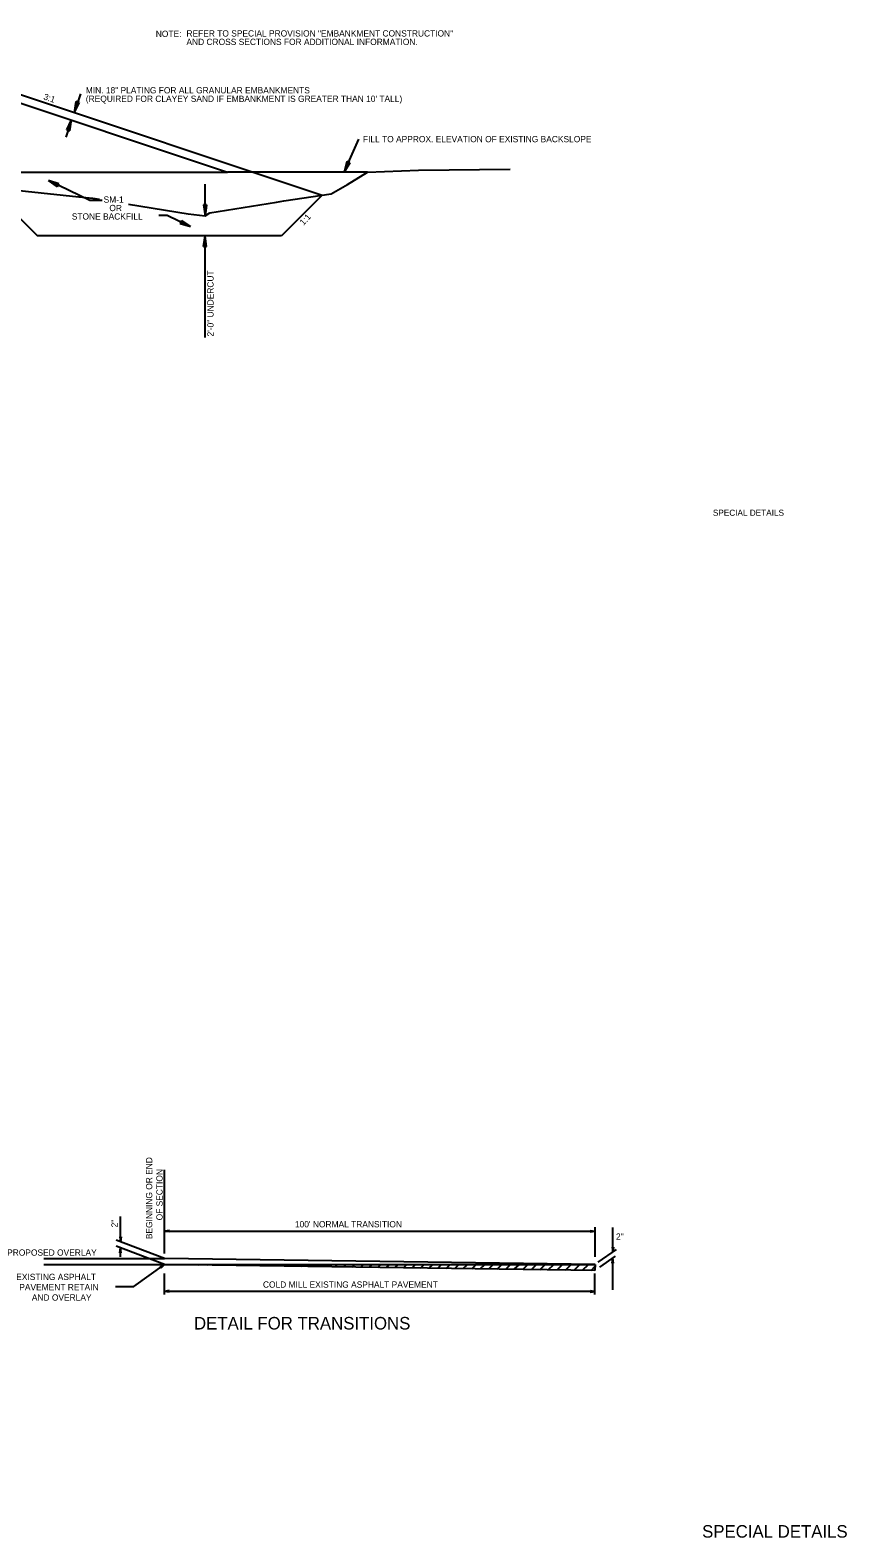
# Model space of a CAD drawing. Extents: x 1035 to 3550, y 35 to 1510.
# Drawn here: x 2769 to 3550, y 35 to 1477 of the extents above; entities that cross this region are included whole.
import ezdxf

# ---------------------------------------------------------------- set-up
doc = ezdxf.new("R2010")
doc.units = 0
for name, color, linetype in [('Default', 7, 'Continuous'), ('G-ANNO-NPLT', 7, 'Continuous'), ('R_Border', 7, 'Continuous'), ('R_Border Notes', 7, 'Continuous'), ('R_Border Prem', 7, 'Continuous'), ('R_Detour Annot', 7, 'Continuous'), ('R_Exist Surface', 7, 'Continuous'), ('R_Fin Surface', 7, 'Continuous'), ('R_Grid', 7, 'Continuous')]:
    doc.layers.add(name, color=color, linetype=linetype)

msp = doc.modelspace()

# ---------------------------------------------------------------- linework, layer by layer
at = {"layer": 'Default'}
for p, q in [((2982.4, 1341.5), (2958, 1341.5)), ((2897.9, 307.1), (2897.9, 387)), ((2855.7, 318.4), (2855.7, 342.4)), ((3309.4, 304), (3309.4, 332.4)), ((3326.3, 308.4), (3326.3, 332)), ((2897.9, 302.4), (2851.5, 319.8)), ((2855, 322.9), (2855.7, 318.4)), ((2855, 322.9), (2855.7, 319.1)), ((2856.3, 322.9), (2855, 322.9)), ((2855.2, 322.9), (2855.7, 320)), ((2855.2, 322.9), (2855.7, 320.7)), ((2855.5, 322.9), (2855.7, 321.5)), ((2855.5, 322.9), (2855.7, 322.2)), ((2856.3, 322.9), (2855.7, 318.4)), ((2855.9, 322.9), (2855.7, 321.5)), ((2856.1, 322.9), (2855.7, 320)), ((2856.1, 322.9), (2855.7, 319.1)), ((2855.9, 322.9), (2855.7, 320.7)), ((2855.7, 322.9), (2855.7, 322.2)), ((2902.5, 329.1), (2897.9, 328.4)), ((2897.9, 328.4), (3309.4, 328.4)), ((2902.5, 327.8), (2897.9, 328.4)), ((2902.5, 328.9), (2898.5, 328.4)), ((2902.5, 327.8), (2898.5, 328.4)), ((2902.5, 328.9), (2899.4, 328.4)), ((2902.5, 328), (2899.4, 328.4)), ((2902.5, 328.7), (2900.3, 328.4)), ((2902.5, 328), (2900.3, 328.4)), ((2902.5, 328.7), (2901, 328.4)), ((2902.5, 328.2), (2901, 328.4)), ((2902.5, 328.4), (2901.9, 328.4)), ((2902.5, 328.2), (2901.9, 328.4)), ((2902.5, 327.8), (2902.5, 329.1)), ((3304.8, 329.1), (3309.4, 328.4)), ((3304.8, 329.1), (3304.8, 327.8)), ((3304.8, 328.9), (3307.9, 328.4)), ((3304.8, 328.9), (3308.5, 328.4)), ((3304.8, 328.7), (3306.3, 328.4)), ((3304.8, 328.7), (3307, 328.4)), ((3304.8, 327.8), (3309.4, 328.4)), ((3304.8, 328.2), (3306.3, 328.4)), ((3304.8, 328), (3307.9, 328.4)), ((3304.8, 327.8), (3308.5, 328.4)), ((3304.8, 328), (3307, 328.4)), ((3304.8, 328.2), (3305.4, 328.4)), ((3304.8, 328.4), (3305.4, 328.4)), ((2897.9, 296.7), (2851.5, 314)), ((2855, 307.8), (2855.7, 312.4)), ((2855, 307.8), (2855.7, 311.8)), ((2855, 307.8), (2856.3, 307.8)), ((2855.2, 307.8), (2855.7, 310.9)), ((2855.2, 307.8), (2855.7, 310.2)), ((2855.5, 307.8), (2855.7, 309.3)), ((2855.5, 307.8), (2855.7, 308.4)), ((2856.3, 307.8), (2855.7, 312.4)), ((2855.7, 304), (2855.7, 312.4)), ((2856.1, 307.8), (2855.7, 311.8)), ((2856.1, 307.8), (2855.7, 310.9)), ((2855.9, 307.8), (2855.7, 310.2)), ((2855.9, 307.8), (2855.7, 309.3)), ((2855.7, 307.8), (2855.7, 308.4)), ((3312.5, 298.9), (3329.8, 310.9)), ((3313.9, 294), (3329, 304.7)), ((3325.6, 313.1), (3326.3, 308.4)), ((3327, 313.1), (3325.6, 313.1)), ((3325.9, 313.1), (3326.3, 310)), ((3325.9, 313.1), (3326.3, 309.3)), ((3326.1, 313.1), (3326.3, 311.6)), ((3326.1, 313.1), (3326.3, 310.9)), ((3327, 313.1), (3326.3, 308.4)), ((3326.5, 313.1), (3326.3, 311.6)), ((3326.7, 313.1), (3326.3, 310)), ((3327, 313.1), (3326.3, 309.3)), ((3326.7, 313.1), (3326.3, 310.9)), ((3326.3, 313.1), (3326.3, 312.4)), ((3326.5, 313.1), (3326.3, 312.4)), ((2782.4, 302.4), (2897.9, 302.4)), ((2782.4, 296.7), (3309.4, 296.7)), ((2868.6, 275.6), (2897.9, 296.7)), ((2893.7, 294.4), (2897.9, 296.7)), ((2893.7, 294.4), (2894.5, 293.3)), ((2893.9, 294.4), (2897.2, 296.2)), ((2893.9, 294.4), (2896.5, 295.8)), ((2893.9, 294.2), (2895.9, 295.3)), ((2893.9, 294.2), (2895.4, 294.9)), ((2894.1, 294), (2894.8, 294.4)), ((2894.1, 294), (2894.8, 294.4)), ((2894.3, 293.6), (2896.5, 295.8)), ((2894.3, 293.8), (2895.9, 295.3)), ((2894.3, 293.8), (2895.4, 294.9)), ((2894.5, 293.3), (2897.9, 296.7)), ((2894.5, 293.6), (2897.2, 296.2)), ((3309.4, 296.7), (2897.9, 302.4)), ((3309.2, 290.9), (2897.9, 296.7)), ((2914.1, 296.4), (2914.3, 296.7)), ((2922.2, 296.3), (2922.5, 296.7)), ((2930.3, 296.2), (2931, 296.7)), ((2938.6, 296.1), (2939.2, 296.7)), ((2946.7, 296), (2947.4, 296.7)), ((2954.8, 295.9), (2955.6, 296.7)), ((2962.9, 295.8), (2963.8, 296.7)), ((2971.2, 295.6), (2972.3, 296.7)), ((2979.3, 295.5), (2980.5, 296.7)), ((2987.7, 295.4), (2988.7, 296.7)), ((2995.6, 295.3), (2996.9, 296.7)), ((3003.9, 295.2), (3005.4, 296.7)), ((3012, 295.1), (3013.6, 296.7)), ((3020.3, 295), (3021.8, 296.7)), ((3028.2, 294.8), (3030.2, 296.7)), ((3036.5, 294.7), (3038.5, 296.7)), ((3044.6, 294.6), (3046.7, 296.7)), ((3052.7, 294.5), (3054.9, 296.7)), ((3060.8, 294.4), (3063.3, 296.7)), ((3069.2, 294.3), (3071.5, 296.7)), ((3077.3, 294.1), (3079.8, 296.7)), ((3085.4, 294), (3088, 296.7)), ((3093.5, 293.9), (3096.4, 296.7)), ((3101.8, 293.8), (3104.6, 296.7)), ((3109.7, 293.7), (3112.9, 296.7)), ((3118, 293.6), (3121.1, 296.7)), ((3126.3, 293.5), (3129.3, 296.7)), ((3134.4, 293.3), (3137.7, 296.7)), ((3142.5, 293.2), (3146, 296.7)), ((3150.6, 293.1), (3154.2, 296.7)), ((3159, 293), (3162.6, 296.7)), ((3167.1, 292.9), (3170.8, 296.7)), ((3175.2, 292.8), (3179.1, 296.7)), ((3183.3, 292.7), (3187.3, 296.7)), ((3191.6, 292.5), (3195.7, 296.7)), ((3199.5, 292.4), (3203.9, 296.7)), ((3207.8, 292.3), (3212.1, 296.7)), ((3215.9, 292.2), (3220.4, 296.7)), ((3224.2, 292.1), (3228.6, 296.7)), ((3232.1, 292), (3237, 296.7)), ((3240.4, 291.9), (3245.2, 296.7)), ((3248.6, 291.8), (3253.5, 296.7)), ((3256.6, 291.6), (3261.7, 296.7)), ((3264.7, 291.5), (3270.1, 296.7)), ((3273.1, 291.4), (3278.3, 296.7)), ((3281.2, 291.3), (3286.6, 296.7)), ((3289.3, 291.2), (3294.8, 296.7)), ((3297.4, 291.1), (3303.2, 296.7)), ((3305.7, 290.9), (3309.3, 294.6)), ((3309.4, 296.7), (3309.2, 290.9)), ((3325.6, 298), (3326.3, 302.7)), ((3325.6, 298), (3327, 298)), ((3325.9, 298), (3326.3, 302)), ((3325.9, 298), (3326.3, 301.1)), ((3326.1, 298), (3326.3, 300.4)), ((3326.1, 298), (3326.3, 299.5)), ((3326.3, 272.5), (3326.3, 302.7)), ((3327, 298), (3326.3, 302.7)), ((3327, 298), (3326.3, 302)), ((3326.7, 298), (3326.3, 301.1)), ((3326.7, 298), (3326.3, 300.4)), ((3326.5, 298), (3326.3, 299.5)), ((3326.5, 298), (3326.3, 298.9)), ((3326.3, 298), (3326.3, 298.9)), ((2851, 275.6), (2868.6, 275.6)), ((2897.9, 268), (2897.9, 288)), ((3309.2, 268), (3309.2, 288)), ((2902.3, 271.6), (2897.9, 270.9)), ((2902.3, 271.6), (2897.9, 270.9)), ((3309.2, 270.9), (2897.9, 270.9)), ((2902.3, 270.2), (2897.9, 270.9)), ((2902.3, 270.2), (2897.9, 270.9)), ((2902.3, 271.6), (2898.5, 270.9)), ((2902.3, 271.6), (2898.5, 270.9)), ((2902.3, 270.5), (2898.5, 270.9)), ((2902.3, 270.5), (2898.5, 270.9)), ((2902.3, 271.4), (2899.4, 270.9)), ((2902.3, 271.4), (2899.4, 270.9)), ((2902.3, 270.5), (2899.4, 270.9)), ((2902.3, 270.5), (2899.4, 270.9)), ((2902.3, 271.4), (2900.1, 270.9)), ((2902.3, 271.4), (2900.1, 270.9)), ((2902.3, 270.7), (2900.1, 270.9)), ((2902.3, 270.7), (2900.1, 270.9)), ((2902.3, 271.1), (2901, 270.9)), ((2902.3, 271.1), (2901, 270.9)), ((2902.3, 270.7), (2901, 270.9)), ((2902.3, 270.7), (2901, 270.9)), ((2902.3, 271.1), (2901.7, 270.9)), ((2902.3, 271.1), (2901.7, 270.9)), ((2902.3, 270.9), (2901.7, 270.9)), ((2902.3, 270.9), (2901.7, 270.9)), ((2902.3, 270.2), (2902.3, 271.6)), ((2902.3, 270.2), (2902.3, 271.6)), ((3304.8, 271.6), (3309.2, 270.9)), ((3304.8, 271.6), (3308.5, 270.9)), ((3304.8, 271.6), (3304.8, 270.2)), ((3304.8, 271.4), (3307.6, 270.9)), ((3304.8, 271.4), (3307, 270.9)), ((3304.8, 271.1), (3306.1, 270.9)), ((3304.8, 271.1), (3305.4, 270.9)), ((3304.8, 270.2), (3309.2, 270.9)), ((3304.8, 270.7), (3306.1, 270.9)), ((3304.8, 270.5), (3307.6, 270.9)), ((3304.8, 270.5), (3308.5, 270.9)), ((3304.8, 270.7), (3307, 270.9)), ((3304.8, 270.9), (3305.4, 270.9))]:
    msp.add_line(p, q, dxfattribs=at)
at = {"layer": 'G-ANNO-NPLT'}
for p, q in [((2817.4, 1416.4), (2811.4, 1398.6)), ((2809, 1391.3), (2803.5, 1374.8)), ((2673.5, 1341.5), (2958, 1341.5)), ((3091.7, 1341.5), (2982.5, 1341.5)), ((2730.3, 1326.9), (2776.5, 1280.6)), ((3048.6, 1319.4), (3009.8, 1280.6)), ((3009.8, 1280.6), (2776.5, 1280.6))]:
    msp.add_line(p, q, dxfattribs=at)
for points in [[(2723.8, 1419.5), (2958, 1341.5)], [(2838.1, 1314.4), (2826.4, 1314.4), (2786.8, 1333.4)], [(2892.3, 1300.2), (2900.4, 1300.2), (2922.8, 1289.4)]]:
    msp.add_lwpolyline(points, dxfattribs=at)
at = {"layer": 'R_Border Prem'}
for p, q in [((2936.6, 1299.7), (2936.6, 1330)), ((2936.6, 1183.2), (2936.6, 1280.6))]:
    msp.add_line(p, q, dxfattribs=at)
at = {"layer": 'R_Detour Annot'}
msp.add_line((3069.4, 1341.5), (3083.6, 1373), dxfattribs=at)
at = {"layer": 'R_Exist Surface'}
for points in [[(2158.7, 1373), (2218.3, 1399.3), (2259.3, 1417.8), (2263.8, 1418), (2273.1, 1418.4), (2317.6, 1419.5), (2322.1, 1419.6), (2383.5, 1420.7), (2385.2, 1420.7), (2432.3, 1419.9), (2447.4, 1419.7), (2447.9, 1419.7), (2497.5, 1418.6), (2498, 1418.5), (2515.3, 1415.2), (2582.8, 1383.3), (2615, 1367.6), (2633.7, 1360.4), (2713.5, 1328.6), (2815.8, 1317.9), (2829.3, 1316.6), (2835.7, 1315.5)], [(2941.2, 1302.6), (3005, 1312.7), (3011.9, 1313.8), (3057.2, 1320.8), (3072.7, 1329.6), (3091.7, 1341.5), (3140.5, 1343.3), (3228.3, 1344.2)], [(2863.4, 1310.9), (2920.3, 1301.4), (2936.8, 1299.7), (2941.2, 1302.6)]]:
    msp.add_lwpolyline(points, dxfattribs=at)
at = {"layer": 'R_Fin Surface'}
msp.add_lwpolyline([(2271.4, 1418.4), (2287.4, 1426.3), (2315.7, 1426.9), (2356.8, 1428.5), (2508.5, 1431.6), (2660.2, 1428.5), (2701.4, 1426.9), (2729.6, 1425.8), (2750.6, 1419), (3048.6, 1319.4)], dxfattribs=at)
at = {"layer": 'R_Grid'}
for p, q in [((2813.2, 1408.9), (2811.4, 1398.6)), ((2816.2, 1407.9), (2811.4, 1398.6)), ((2813.5, 1408.8), (2812, 1400.2)), ((2815.9, 1408), (2812, 1400.2)), ((2813.7, 1408.7), (2812.5, 1401.9)), ((2815.7, 1408), (2812.5, 1401.9)), ((2814, 1408.6), (2813.1, 1403.5)), ((2815.4, 1408.1), (2813.1, 1403.5)), ((2816.2, 1407.9), (2813.2, 1408.9)), ((2814.2, 1408.5), (2813.6, 1405.2)), ((2815.2, 1408.2), (2813.6, 1405.2)), ((2814.5, 1408.4), (2814.2, 1406.8)), ((2814.9, 1408.3), (2814.2, 1406.8)), ((2804.3, 1382), (2809, 1391.3)), ((2804.5, 1381.9), (2808.5, 1389.7)), ((2804.8, 1381.9), (2807.9, 1388)), ((2805, 1381.8), (2807.4, 1386.4)), ((2805.3, 1381.7), (2806.8, 1384.7)), ((2806.2, 1381.4), (2806.8, 1384.7)), ((2806.5, 1381.3), (2807.4, 1386.4)), ((2806.7, 1381.2), (2807.9, 1388)), ((2807, 1381.1), (2808.5, 1389.7)), ((2807.2, 1381), (2809, 1391.3)), ((2804.3, 1382), (2807.2, 1381)), ((2805.5, 1381.6), (2806.3, 1383.1)), ((2806, 1381.5), (2806.3, 1383.1)), ((3072.2, 1351.5), (3069.4, 1341.5)), ((3075, 1350.2), (3069.4, 1341.5)), ((3072.4, 1351.4), (3070.1, 1343.1)), ((3074.8, 1350.3), (3070.1, 1343.1)), ((3072.7, 1351.3), (3070.8, 1344.7)), ((3074.5, 1350.4), (3070.8, 1344.7)), ((3072.9, 1351.2), (3071.5, 1346.2)), ((3074.3, 1350.6), (3071.5, 1346.2)), ((3075, 1350.2), (3072.2, 1351.5)), ((3073.2, 1351.1), (3072.2, 1347.8)), ((3074.1, 1350.7), (3072.2, 1347.8)), ((3073.4, 1351), (3072.9, 1349.4)), ((3073.8, 1350.8), (3072.9, 1349.4)), ((2795.4, 1327.5), (2786.8, 1333.4)), ((2796.8, 1330.3), (2786.8, 1333.4)), ((2795.5, 1327.8), (2788.4, 1332.6)), ((2796.7, 1330.1), (2788.4, 1332.6)), ((2796.5, 1329.9), (2790, 1331.9)), ((2795.7, 1328), (2790, 1331.9)), ((2795.8, 1328.2), (2791.5, 1331.1)), ((2796.4, 1329.6), (2791.5, 1331.1)), ((2796.3, 1329.4), (2793.1, 1330.4)), ((2795.9, 1328.5), (2793.1, 1330.4)), ((2796.2, 1329.1), (2794.6, 1329.6)), ((2796, 1328.7), (2794.6, 1329.6)), ((2795.4, 1327.5), (2796.8, 1330.3)), ((2935, 1310), (2936.6, 1299.7)), ((2938.1, 1310), (2935, 1310)), ((2935.3, 1310), (2936.6, 1301.5)), ((2935.6, 1310), (2936.6, 1303.2)), ((2935.8, 1310), (2936.6, 1304.9)), ((2936.1, 1310), (2936.6, 1306.7)), ((2936.3, 1310), (2936.6, 1308.4)), ((2938.1, 1310), (2936.6, 1299.7)), ((2937.1, 1310), (2936.6, 1306.7)), ((2937.6, 1310), (2936.6, 1303.2)), ((2937.9, 1310), (2936.6, 1301.5)), ((2937.4, 1310), (2936.6, 1304.9)), ((2936.8, 1310), (2936.6, 1308.4)), ((2914.2, 1295.2), (2912.8, 1292.4)), ((2912.8, 1292.4), (2922.8, 1289.4)), ((2912.9, 1292.7), (2921.2, 1290.1)), ((2913.1, 1292.9), (2919.6, 1290.9)), ((2913.2, 1293.1), (2918.1, 1291.6)), ((2913.3, 1293.4), (2916.5, 1292.4)), ((2913.4, 1293.6), (2915, 1293.1)), ((2913.6, 1294.1), (2915, 1293.1)), ((2913.7, 1294.3), (2916.5, 1292.4)), ((2913.8, 1294.5), (2918.1, 1291.6)), ((2913.9, 1294.8), (2919.6, 1290.9)), ((2914.1, 1295), (2921.2, 1290.1)), ((2914.2, 1295.2), (2922.8, 1289.4)), ((2935, 1270.3), (2936.6, 1280.6)), ((2935, 1270.3), (2938.1, 1270.3)), ((2935.3, 1270.3), (2936.6, 1278.9)), ((2935.6, 1270.3), (2936.6, 1277.1)), ((2935.8, 1270.3), (2936.6, 1275.4)), ((2936.1, 1270.3), (2936.6, 1273.6)), ((2936.3, 1270.3), (2936.6, 1271.9)), ((2938.1, 1270.3), (2936.6, 1280.6)), ((2937.9, 1270.3), (2936.6, 1278.9)), ((2937.6, 1270.3), (2936.6, 1277.1)), ((2937.4, 1270.3), (2936.6, 1275.4)), ((2937.1, 1270.3), (2936.6, 1273.6)), ((2936.8, 1270.3), (2936.6, 1271.9))]:
    msp.add_line(p, q, dxfattribs=at)

# ---------------------------------------------------------------- texts
at = {"layer": 'Default'}
for s, p in [('BEGINNING OR END', (2886.1, 320.8)), ('OF SECTION', (2896, 338.8)), ('2"', (2853, 332.1))]:
    msp.add_text(s, height=6, rotation=90, dxfattribs=at).set_placement(p)
for s, height, p in [("100' NORMAL TRANSITION", 6, (3022.5, 332.1)), ('2"', 6, (3329.4, 320.3)), ('PROPOSED OVERLAY', 6, (2747.4, 305)), ('EXISTING ASPHALT', 6, (2756.1, 281.7)), ('PAVEMENT RETAIN', 6, (2759, 271.9)), ('COLD MILL EXISTING ASPHALT PAVEMENT', 6, (2991.9, 274.4)), ('AND OVERLAY', 6, (2771, 262)), ('DETAIL FOR TRANSITIONS', 12, (2926, 234.4))]:
    msp.add_text(s, height=height, dxfattribs=at).set_placement(p)
at = {"layer": 'G-ANNO-NPLT'}
for s, p in [('NOTE:', (2889.5, 1470.7)), ('REFER TO SPECIAL PROVISION "EMBANKMENT CONSTRUCTION"', (2918.8, 1471.1)), ('AND CROSS SECTIONS FOR ADDITIONAL INFORMATION.', (2918.8, 1463)), ("(REQUIRED FOR CLAYEY SAND IF EMBANKMENT IS GREATER THAN 10' TALL)", (2822.6, 1408.6)), ('MIN. 18" PLATING FOR ALL GRANULAR EMBANKMENTS', (2822.6, 1416.7)), ('SM-1', (2839.6, 1312.2)), ('STONE BACKFILL', (2809.2, 1296)), ('OR', (2845.1, 1304.1))]:
    msp.add_text(s, height=6, dxfattribs=at).set_placement(p)
for s, rotation, p in [('3:1', 341.565, (2781.6, 1411.1)), ('2\'-0" UNDERCUT', 90, (2944.7, 1184.2))]:
    msp.add_text(s, height=6, rotation=rotation, dxfattribs=at).set_placement(p)
at = {"layer": 'R_Border'}
msp.add_text('SPECIAL DETAILS', height=12, dxfattribs=at).set_placement((3411.7, 35.3))
at = {"layer": 'R_Border Notes'}
msp.add_text('1:1', height=6, rotation=47.1744, dxfattribs=at).set_placement((3030.7, 1290))
at = {"layer": 'R_Border Prem'}
msp.add_text('SPECIAL DETAILS', height=5.862, dxfattribs=at).set_placement((3422, 1012.7))
at = {"layer": 'R_Detour Annot'}
msp.add_text('FILL TO APPROX. ELEVATION OF EXISTING BACKSLOPE', height=6, dxfattribs=at).set_placement((3087.5, 1370))

doc.saveas('drawing.dxf')
